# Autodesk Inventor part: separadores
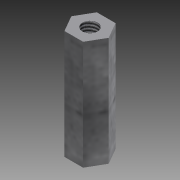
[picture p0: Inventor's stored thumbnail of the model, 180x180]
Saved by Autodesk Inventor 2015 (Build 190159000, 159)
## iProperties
Created: 2016-06
Part Number: separadores
Material: Genérico
Document SubType Name: Modeling
Designer: Diego
Density: 1 g/cm^3
Appearance: Valor por defecto
Author: Diego
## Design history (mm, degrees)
sketch "Boceto1"
  geometry: L1 (-6, 0)-(-3, 5.196); L2 (-3, 5.196)-(3, 5.196); L3 (3, 5.196)-(6, 0); L4 (6, 0)-(3, -5.196); L5 (3, -5.196)-(-3, -5.196); L6 (-6, 0)-(-3, -5.196); A1 r 6 centre (0, 0) between (-6, 0) and (-3, 5.196); 1 further point
  constraints: 12 end point, 6 point on circle, 3 parallel, 1 centre point, 1 coincident
  dimensions: "d0" = 12 diameter of A1; "d1" = 6 distance of L1.start L1.end; "d2" = 6 distance of L1.end L2.end; "d3" = 6 distance of L2.end L3.end
extrude "Extrusión1" new body sketch "Boceto1" distance "d4" = 35; taper "d5" = 0 deg
sketch "Boceto2"
  geometry: 2 further points
  constraints: 1 coincident
hole "Agujero1" sketch "Boceto2" at (0, 0) diameter "d6" = 4.917; stored, may be unused: countersink angle "d10" = 90 deg, drill point angle "d12" = 118 deg; dims "d7" = 35, "d8" = 4, "d9" = 2, "d11" = 36
node "Sólido1"
